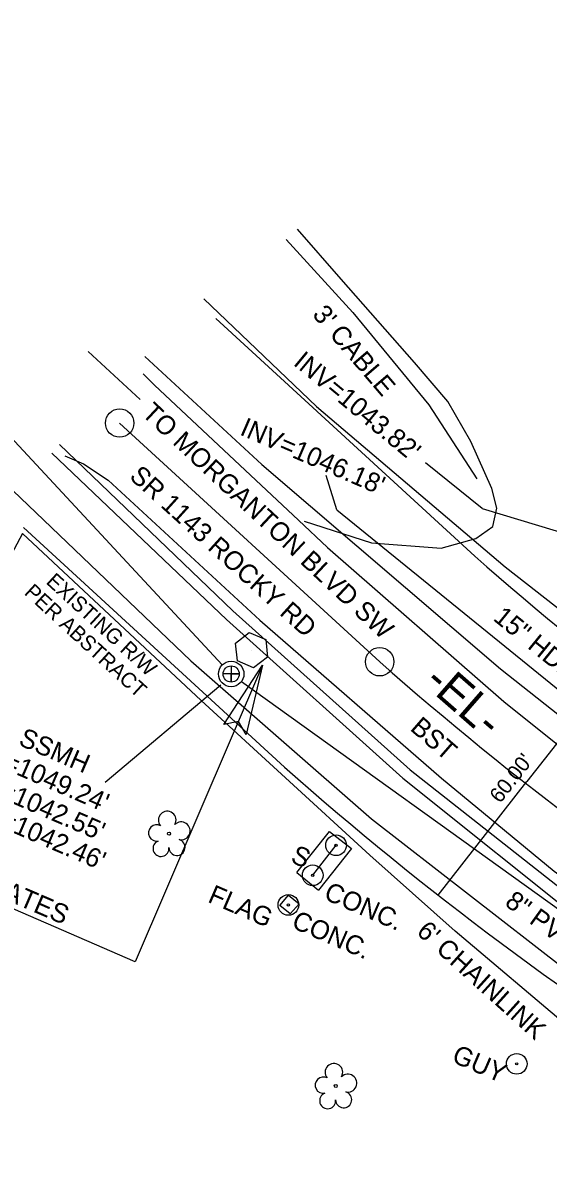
# Model space of a CAD drawing. Extents: x 1230592 to 1231575, y 779497 to 780221.
# Drawn here: x 1230719.7 to 1230830.6, y 779941.5 to 780183.6 of the extents above; entities that cross this region are included whole.
import ezdxf

# ---------------------------------------------------------------- set-up
doc = ezdxf.new("R2010")
doc.units = 0
for name, color, linetype in [('CTL GPS Vertical CELL', 7, 'Continuous'), ('CTL Supplemental Horizontal and Vertical Text', 7, 'Continuous'), ('Default', 7, 'Continuous'), ('Exist Horizontal Alignment', 7, 'Continuous'), ('Exist Horizontal Alignment Direction Label', 7, 'Continuous'), ('Exist Horizontal Alignment Point', 7, 'Continuous'), ('Exist Other Culture Anchor (Guy Wire) CELL', 7, 'Continuous'), ('Exist Other Culture Anchor (Guy Wire) Text', 7, 'Continuous'), ('Exist Other Culture Fence Line', 7, 'Continuous'), ('Exist Other Culture Fence Line Text', 7, 'Continuous'), ('Exist Other Culture Sign CELL', 7, 'Continuous'), ('Exist Other Culture Sign Text', 7, 'Continuous'), ('Exist Right of Way Line', 7, 'Continuous'), ('Exist Right of Way Line Text', 7, 'Continuous'), ('Exist Right of Way Width CELL', 7, 'Continuous'), ('Exist Roads EOP', 7, 'Continuous'), ('Exist Roads EOP Leader', 7, 'Continuous'), ('Exist Roads EOP Other', 7, 'Continuous'), ('Exist Roads EOP Other Text', 7, 'Continuous'), ('Exist Roads EOP Text', 7, 'Continuous'), ('Exist Structure Minor Pipes HDPE 15 Inch', 7, 'Continuous'), ('Exist Structure Minor Pipes HDPE 15 Inch Invert', 7, 'Continuous'), ('Exist Structure Minor Pipes HDPE 15 Inch Leader', 7, 'Continuous'), ('Exist Structure Minor Pipes HDPE 15 Inch Text', 7, 'Continuous'), ('Exist Utilities Sanitary Sewer Forced Main SUE', 7, 'Continuous'), ('Exist Utilities Sanitary Sewer Manhole CELL', 7, 'Continuous'), ('Exist Utilities Sanitary Sewer Manhole Text', 7, 'Continuous'), ('Exist Utilities Sanitary Sewer UG Line', 7, 'Continuous'), ('Exist Utilities Sanitary Sewer UG Line Invert Elevation', 7, 'Continuous'), ('Exist Utilities Sanitary Sewer UG Line Text', 7, 'Continuous'), ('Exist Utilities Telephone UG Cable SUE', 7, 'Continuous'), ('Exist Utilities Telephone UG FO SUE', 7, 'Continuous'), ('Exist Utilities Water UG Line SUE', 7, 'Continuous'), ('Exist Vegetation Tree CELL', 7, 'Continuous'), ('Old_Level_11', 7, 'Continuous')]:
    doc.layers.add(name, color=color, linetype=linetype)

msp = doc.modelspace()

# ---------------------------------------------------------------- linework, layer by layer
at = {"layer": 'CTL GPS Vertical CELL'}
msp.add_line((1230767.97, 780051.14), (1230767.97, 780051.14), dxfattribs=at)
msp.add_lwpolyline([(1230770.97, 780053.36), (1230771.34, 780049.66), (1230768.41, 780047.38), (1230765.01, 780048.91), (1230764.57, 780052.64), (1230767.5, 780054.86)], close=True, dxfattribs=at)
at = {"layer": 'Default'}
for p, q in [((1230770.31, 780047.97), (1230743.44, 779985.31)), ((1230743.44, 779985.31), (1230631.91, 780033.62))]:
    msp.add_line(p, q, dxfattribs=at)
at = {"layer": 'Exist Horizontal Alignment'}
msp.add_line((1230740.13, 780099.1), (1230795.04, 780048.69), dxfattribs=at)
msp.add_arc((1231236.73, 780547.78), 666.47, 228.49205, 247.86063, dxfattribs=at)
at = {"layer": 'Exist Horizontal Alignment Point'}
for centre in [(1230740.13, 780099.1), (1230795.04, 780048.69)]:
    msp.add_circle(centre, 3, dxfattribs=at)
at = {"layer": 'Exist Other Culture Anchor (Guy Wire) CELL'}
for radius in [2.18, 0.24]:
    msp.add_circle((1230823.97, 779963.77), radius, dxfattribs=at)
at = {"layer": 'Exist Other Culture Fence Line'}
for points in [[(1230775.26, 780137.9), (1230789.33, 780122.47), (1230805.39, 780102.93), (1230815.51, 780087.35)], [(1230880.25, 779941.6), (1230853.18, 779957.14), (1230835.11, 779971.4), (1230810.95, 779991.8), (1230792.98, 780007.87), (1230757.31, 780040.54), (1230719.63, 780075.75), (1230711.33, 780060.3), (1230695.77, 780031.77)]]:
    msp.add_lwpolyline(points, dxfattribs=at)
at = {"layer": 'Exist Other Culture Sign CELL'}
msp.add_line((1230780.9, 780003.6), (1230785.83, 780009.94), dxfattribs=at)
for centre, radius in [((1230785.83, 780009.94), 2.18), ((1230785.83, 780009.94), 0.24), ((1230780.9, 780003.6), 2.18), ((1230780.9, 780003.6), 0.24), ((1230775.76, 779997.33), 2.18), ((1230775.76, 779997.33), 0.24)]:
    msp.add_circle(centre, radius, dxfattribs=at)
at = {"layer": 'Exist Right of Way Line'}
for p, q in [((1230760.41, 780121.2), (1230815.13, 780070.97)), ((1230719.84, 780077.01), (1230774.95, 780026.4))]:
    msp.add_line(p, q, dxfattribs=at)
for radius, start, end in [(636.47, 228.51644, 247.88383), (696.47, 228.46926, 247.83894)]:
    msp.add_arc((1231236.73, 780547.78), radius, start, end, dxfattribs=at)
at = {"layer": 'Exist Right of Way Width CELL'}
for p in [(1230844.35, 780046.65), (1230807.36, 779999.41)]:
    msp.add_line(p, (1230826.13, 780023.38), dxfattribs=at)
at = {"layer": 'Exist Roads EOP'}
for points in [[(1230779.12, 780078.37), (1230793.31, 780073.8), (1230808.01, 780072.67), (1230815.31, 780074.71), (1230818.89, 780077.22), (1230819.76, 780081.1), (1230818.72, 780085.31), (1230814.31, 780095.19), (1230809.45, 780103.63), (1230802.38, 780111.87), (1230786.9, 780129.47), (1230777.68, 780140.04)], [(1230745.08, 780109.47), (1230747.52, 780107.09), (1230777.89, 780078.62), (1230784.03, 780072.85), (1230821.26, 780040.32), (1230843.51, 780022.46), (1230853.3, 780015.49), (1230860.24, 780010.5), (1230880.46, 779996.53), (1230901.4, 779983.72), (1230925.05, 779970.38), (1230944.72, 779960.26), (1230989.99, 779941.18)], [(1230728.53, 780092.2), (1230732.49, 780090.47), (1230737.68, 780087.05), (1230769.7, 780057.47), (1230808.1, 780024.07), (1230831.85, 780004.44), (1230847.98, 779992.92), (1230872.92, 779976.6), (1230890.76, 779965.67), (1230913.98, 779952.92), (1230935.97, 779942.19), (1230975.27, 779923.5), (1230980.9, 779919.78)]]:
    msp.add_lwpolyline(points, dxfattribs=at)
at = {"layer": 'Exist Roads EOP Leader'}
msp.add_lwpolyline([(1230733.51, 780114.19), (1230744.47, 780104.05)], dxfattribs=at)
at = {"layer": 'Exist Roads EOP Other'}
for p, q in [((1230777.52, 780004.19), (1230782.11, 780000.45)), ((1230773.98, 779997.2), (1230775.8, 779999.38))]:
    msp.add_line(p, q, dxfattribs=at)
for points in [[(1230777.52, 780004.19), (1230784.43, 780012.87), (1230789.11, 780009.24), (1230782.11, 780000.45)], [(1230775.8, 779999.38), (1230778, 779997.56), (1230776.1, 779995.45), (1230773.98, 779997.2)]]:
    msp.add_lwpolyline(points, dxfattribs=at)
at = {"layer": 'Exist Structure Minor Pipes HDPE 15 Inch'}
for p, q in [((1230785.97, 780080.77), (1230864.82, 780016.7)), ((1230816.7, 780081.08), (1230893.31, 780057.75))]:
    msp.add_line(p, q, dxfattribs=at)
at = {"layer": 'Exist Structure Minor Pipes HDPE 15 Inch Leader'}
for points in [[(1230816.7, 780081.08), (1230804.71, 780090.71)], [(1230785.97, 780080.77), (1230783.75, 780088.03)]]:
    msp.add_lwpolyline(points, dxfattribs=at)
at = {"layer": 'Exist Utilities Sanitary Sewer Forced Main SUE'}
msp.add_lwpolyline([(1230757.9, 780125.31), (1230781.72, 780102.58), (1230821.53, 780068.76), (1230860.17, 780038.53), (1230889.66, 780019.35), (1230905.72, 780010.18), (1230913.11, 780005.64), (1230917.57, 780007.15), (1230931.25, 780011.67), (1230936.47, 780010.56)], dxfattribs=at)
at = {"layer": 'Exist Utilities Sanitary Sewer Manhole CELL'}
msp.add_lwpolyline([(1230763.68, 780047.83), (1230763.68, 780044.4), (1230763.68, 780046.11), (1230765.39, 780046.11), (1230761.97, 780046.11)], dxfattribs=at)
for radius in [2.69, 1.71]:
    msp.add_circle((1230763.68, 780046.11), radius, dxfattribs=at)
at = {"layer": 'Exist Utilities Sanitary Sewer Manhole Text'}
msp.add_lwpolyline([(1230761.52, 780043.76), (1230737.05, 780023.21)], dxfattribs=at)
at = {"layer": 'Exist Utilities Sanitary Sewer UG Line'}
for p, q in [((1230761.76, 780048.01), (1230635.96, 780183.61)), ((1230765.87, 780044.54), (1230919.53, 779934.09))]:
    msp.add_line(p, q, dxfattribs=at)
at = {"layer": 'Exist Utilities Telephone UG Cable SUE'}
for points in [[(1230725.79, 780092.76), (1230762.7, 780057.62), (1230799.95, 780024.08), (1230839.56, 779992.45), (1230851.92, 779985.96), (1230865.71, 779976.72), (1230881.08, 779963.61), (1230925.1, 779940.03), (1230952.92, 779923.05), (1230969.39, 779909.31), (1230971.4, 779908.18)], [(1230727.4, 780094.55), (1230764.04, 780059.47), (1230801.45, 780025.84), (1230841.13, 779994.59), (1230852.38, 779986.88), (1230859.01, 779982.58), (1230858.9, 779978.86), (1230855.27, 779973.3), (1230851.52, 779966.28), (1230851.69, 779965.12)]]:
    msp.add_lwpolyline(points, dxfattribs=at)
at = {"layer": 'Exist Utilities Telephone UG FO SUE'}
msp.add_lwpolyline([(1230717.56, 780084.84), (1230755.17, 780048.89), (1230793.32, 780015.51), (1230834.26, 779983.7), (1230859.68, 779966.46), (1230875.86, 779956.24), (1230911.92, 779932.25), (1230957.32, 779909.15), (1230963.62, 779906.34), (1230967.97, 779905.69), (1230971.46, 779906.77), (1230971.4, 779908.18)], dxfattribs=at)
at = {"layer": 'Exist Utilities Water UG Line SUE'}
msp.add_lwpolyline([(1230745.46, 780113.17), (1230770.14, 780090.37), (1230820.51, 780047.2), (1230859.23, 780016.55), (1230869.67, 780007.67), (1230886.8, 779998.27), (1230911.3, 779983.42), (1230931.06, 779975.25), (1230939.35, 779971.91), (1230942.18, 779970.99), (1230945.7, 779969.55), (1230949.24, 779968.31), (1230955.39, 779966.4), (1230978.2, 779957.72), (1230978.2, 779957.72)], dxfattribs=at)
at = {"layer": 'Exist Vegetation Tree CELL'}
for p, q in [((1230750.57, 780012.38), (1230750.57, 780012.38)), ((1230785.76, 779959.1), (1230785.76, 779959.1))]:
    msp.add_line(p, q, dxfattribs=at)
for centre in [(1230750.57, 780012.38), (1230785.76, 779959.1)]:
    msp.add_circle(centre, 0.326, dxfattribs=at)
for centre, radius, start, end in [((1230750.18, 780015.25), 1.86, 330.1651, 219.7134), ((1230753.11, 780012.97), 1.9, 257.1011, 134.1999), ((1230747.96, 780012.53), 1.73, 62.6636, 279.3457), ((1230748.86, 780009.26), 1.69, 111.5671, 6.231), ((1230752.24, 780009.48), 1.7, 181.2822, 74.56), ((1230785.37, 779961.98), 1.86, 330.1651, 219.7134), ((1230788.31, 779959.69), 1.9, 257.1011, 134.1999), ((1230783.15, 779959.26), 1.73, 62.6636, 279.3457), ((1230784.05, 779955.98), 1.69, 111.5671, 6.231), ((1230787.43, 779956.2), 1.7, 181.2822, 74.56)]:
    msp.add_arc(centre, radius, start, end, dxfattribs=at)
at = {"layer": 'Old_Level_11'}
msp.add_lwpolyline([(1230762.16, 780035.42), (1230770.31, 780047.97), (1230766.87, 780033.31), (1230765.2, 780036.07)], close=True, dxfattribs=at)

# ---------------------------------------------------------------- texts
at = {"layer": 'CTL Supplemental Horizontal and Vertical Text'}
msp.add_text('LOCALIZED PROJECT COORDINATES', height=4.055, rotation=336.6486, dxfattribs=at).set_placement((1230638.13, 780032.04))
at = {"layer": 'Exist Horizontal Alignment Direction Label'}
msp.add_text('-EL-', height=7, rotation=318.8559, dxfattribs=at).set_placement((1230804.1, 780043.93))
at = {"layer": 'Exist Other Culture Anchor (Guy Wire) Text'}
msp.add_text('GUY', height=4, rotation=336.5812, dxfattribs=at).set_placement((1230810.03, 779964.27))
at = {"layer": 'Exist Other Culture Fence Line Text'}
for s, rotation, p in [("3' CABLE", 310.6421, (1230780.65, 780121.92)), ("6' CHAINLINK", 317.9874, (1230802.61, 779991.37))]:
    msp.add_text(s, height=4, rotation=rotation, dxfattribs=at).set_placement(p)
at = {"layer": 'Exist Other Culture Sign Text'}
for s, p in [('S', (1230776.02, 780006.44)), ('FLAG', (1230758.53, 779998.04))]:
    msp.add_text(s, height=4, rotation=336.5812, dxfattribs=at).set_placement(p)
at = {"layer": 'Exist Right of Way Line Text'}
for s, p in [('EXISTING R/W', (1230724.41, 780065.36)), ('PER ABSTRACT', (1230719.81, 780063.07))]:
    msp.add_text(s, height=3.2, rotation=317.4453, dxfattribs=at).set_placement(p)
at = {"layer": 'Exist Right of Way Width CELL'}
msp.add_text("60.00'", height=3.2, rotation=51.9393, dxfattribs=at).set_placement((1230820.47, 780018.63))
at = {"layer": 'Exist Roads EOP Other Text'}
for p in [(1230783.01, 779998.66), (1230776.2, 779992.62)]:
    msp.add_text('CONC.', height=4, rotation=336.5812, dxfattribs=at).set_placement(p)
at = {"layer": 'Exist Roads EOP Text'}
for s, rotation, p in [('TO MORGANTON BLVD SW', 316.945, (1230744.6, 780100.88)), ('SR 1143 ROCKY RD', 317.7959, (1230741.98, 780087.54)), ('BST', 318.9845, (1230801.26, 780034.38))]:
    msp.add_text(s, height=4, rotation=rotation, dxfattribs=at).set_placement(p)
at = {"layer": 'Exist Structure Minor Pipes HDPE 15 Inch Invert'}
for s, rotation, p in [("INV=1043.82'", 320.4559, (1230776.6, 780111.5)), ("INV=1046.18'", 336.5812, (1230765.29, 780096.72))]:
    msp.add_text(s, height=4, rotation=rotation, dxfattribs=at).set_placement(p)
at = {"layer": 'Exist Structure Minor Pipes HDPE 15 Inch Text'}
msp.add_text('15" HDPE', height=4, rotation=320.9034, dxfattribs=at).set_placement((1230818.79, 780057.6))
at = {"layer": 'Exist Utilities Sanitary Sewer Manhole Text'}
for s, p in [("TOP=1049.24'", (1230705.14, 780030.57)), ('SSMH', (1230718.56, 780031.2))]:
    msp.add_text(s, height=4, rotation=336.5812, dxfattribs=at).set_placement(p)
at = {"layer": 'Exist Utilities Sanitary Sewer UG Line Invert Elevation'}
for s, p in [("INV IN=1042.55'", (1230699.94, 780026.37)), ("INV OUT=1042.46'", (1230694.62, 780022.53))]:
    msp.add_text(s, height=4, rotation=336.5812, dxfattribs=at).set_placement(p)
at = {"layer": 'Exist Utilities Sanitary Sewer UG Line Text'}
msp.add_text('8" PVC', height=4, rotation=324.2911, dxfattribs=at).set_placement((1230821.22, 779997.36))

doc.saveas('drawing.dxf')
